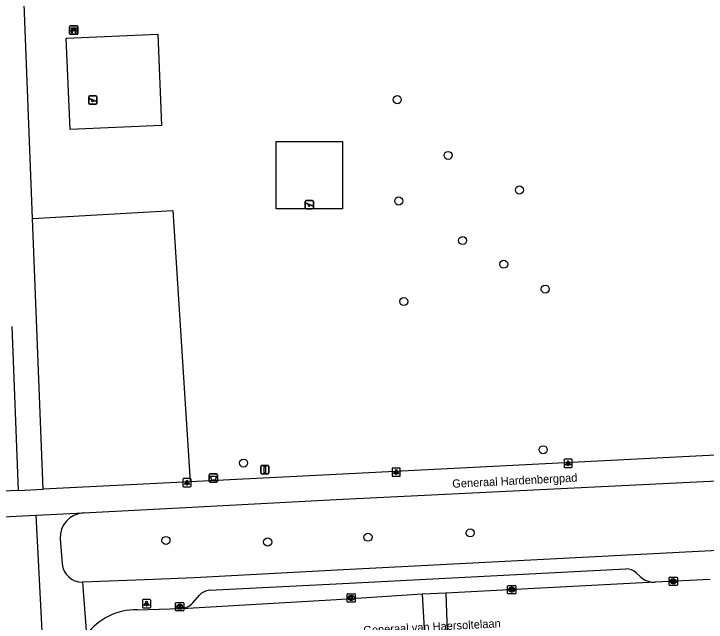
# Model space of a CAD drawing. Extents: x 161084 to 161928, y 385355 to 386522.
# Drawn here: x 161461 to 161544.8, y 386008.9 to 386082.6 of the extents above; entities that cross this region are included whole.
import ezdxf

# ---------------------------------------------------------------- set-up
doc = ezdxf.new("R2010")
doc.units = 0
for name, color, linetype in [('IMGEO_Afvalbak', 7, 'Continuous'), ('IMGEO_Bank', 7, 'Continuous'), ('IMGEO_Boom', 7, 'Continuous'), ('IMGEO_Groenvoorziening', 7, 'Continuous'), ('IMGEO_Kolk', 7, 'Continuous'), ('IMGEO_Lichtpunt', 7, 'Continuous'), ('IMGEO_Openbare_ruimte_label', 7, 'Continuous'), ('IMGEO_Rijbaan_lokaal_open', 7, 'Continuous'), ('IMGEO_Speelvoorziening', 7, 'Continuous'), ('IMGEO_Verkeersbordpaal', 7, 'Continuous'), ('IMGEO_Voetpad_halfverhard', 7, 'Continuous'), ('IMGEO_Voetpad_open', 7, 'Continuous')]:
    doc.layers.add(name, color=color, linetype=linetype)

msp = doc.modelspace()

# ---------------------------------------------------------------- linework, layer by layer
at = {"layer": 'IMGEO_Afvalbak'}
for p, q in [((161484.644, 386025.959), (161484.644, 386026.759)), ((161484.644, 386026.759), (161484.644, 386025.959)), ((161484.744, 386026.859), (161485.534, 386026.859)), ((161485.534, 386026.859), (161484.744, 386026.859)), ((161485.634, 386026.759), (161485.634, 386025.959)), ((161485.634, 386025.959), (161485.634, 386026.759)), ((161485.534, 386025.859), (161484.744, 386025.859)), ((161484.744, 386025.859), (161485.534, 386025.859))]:
    msp.add_line(p, q, dxfattribs=at)
msp.add_lwpolyline([(161484.787, 386026.573), (161485.491, 386026.573), (161485.342, 386026.103), (161484.936, 386026.103), (161484.787, 386026.573)], dxfattribs=at)
for centre, start, end in [((161484.744, 386026.759), 90, 180), ((161484.744, 386026.759), 90, 180), ((161485.534, 386026.759), 0, 90), ((161485.534, 386026.759), 360, 90), ((161484.744, 386025.959), 180, 270), ((161484.744, 386025.959), 180, 270), ((161485.534, 386025.959), 270, 0), ((161485.534, 386025.959), 270, 0)]:
    msp.add_arc(centre, 0.1, start, end, dxfattribs=at)
at = {"layer": 'IMGEO_Bank'}
for p, q in [((161467.729, 386080.215), (161467.729, 386081.056)), ((161467.729, 386081.056), (161467.729, 386080.215)), ((161467.804, 386081.14), (161468.645, 386081.14)), ((161468.645, 386081.14), (161467.804, 386081.14)), ((161468.426, 386080.538), (161468.033, 386080.538)), ((161468.038, 386080.646), (161468.038, 386080.752)), ((161468.082, 386080.752), (161468.082, 386080.646)), ((161468.37, 386080.758), (161468.088, 386080.758)), ((161468.088, 386080.64), (161468.37, 386080.64)), ((161468.376, 386080.646), (161468.376, 386080.752)), ((161468.42, 386080.752), (161468.42, 386080.646)), ((161468.729, 386081.065), (161468.729, 386080.224)), ((161468.729, 386080.224), (161468.729, 386081.065)), ((161468.654, 386080.14), (161467.813, 386080.14)), ((161467.813, 386080.14), (161468.654, 386080.14))]:
    msp.add_line(p, q, dxfattribs=at)
for points in [[(161467.976, 386080.538), (161467.834, 386080.538), (161467.946, 386080.64), (161468.032, 386080.64)], [(161468.032, 386080.758), (161467.946, 386080.758), (161467.946, 386080.919), (161468.509, 386080.919), (161468.509, 386080.758), (161468.426, 386080.758)], [(161468.026, 386080.531), (161468.026, 386080.324), (161467.983, 386080.324), (161467.983, 386080.531)], [(161468.426, 386080.64), (161468.509, 386080.64), (161468.621, 386080.538), (161468.482, 386080.538)], [(161468.476, 386080.531), (161468.476, 386080.324), (161468.432, 386080.324), (161468.432, 386080.531)]]:
    msp.add_lwpolyline(points, dxfattribs=at)
for centre, radius, start, end in [((161467.807, 386081.062), 0.0779, 92.4484, 184.28452), ((161467.807, 386081.062), 0.0779, 92.4484, 184.28452), ((161467.976, 386080.531), 0.00671, 2.89567, 87.10433), ((161468.033, 386080.531), 0.00671, 92.89567, 177.10433), ((161468.031, 386080.751), 0.00671, 2.89567, 87.10433), ((161468.031, 386080.647), 0.00671, 272.89567, 357.10433), ((161468.088, 386080.751), 0.00671, 92.89567, 177.10433), ((161468.088, 386080.647), 0.00671, 182.89567, 267.10433), ((161468.37, 386080.751), 0.00671, 2.89567, 87.10433), ((161468.37, 386080.647), 0.00671, 272.89567, 357.10433), ((161468.427, 386080.751), 0.00671, 92.89567, 177.10433), ((161468.427, 386080.647), 0.00671, 182.89567, 267.10433), ((161468.425, 386080.531), 0.00671, 2.89567, 87.10433), ((161468.482, 386080.531), 0.00671, 92.89567, 177.10433), ((161468.651, 386081.062), 0.0779, 2.4484, 94.28452), ((161468.651, 386081.062), 0.0779, 2.4484, 94.28452), ((161467.807, 386080.218), 0.0779, 182.4484, 274.28452), ((161467.807, 386080.218), 0.0779, 182.4484, 274.28452), ((161468.651, 386080.218), 0.0779, 272.4484, 4.28452), ((161468.651, 386080.218), 0.0779, 272.4484, 4.28452)]:
    msp.add_arc(centre, radius, start, end, dxfattribs=at)
at = {"layer": 'IMGEO_Boom'}
for centre in [(161507.41, 386072.212), (161513.567, 386065.457), (161522.204, 386061.262), (161507.588, 386059.932), (161515.323, 386055.142), (161520.306, 386052.275), (161525.328, 386049.255), (161508.198, 386047.752), (161525.077, 386029.792), (161488.796, 386028.181), (161516.246, 386019.719), (161479.401, 386018.801), (161503.865, 386019.196), (161491.714, 386018.614)]:
    msp.add_circle(centre, 0.489, dxfattribs=at)
at = {"layer": 'IMGEO_Groenvoorziening'}
for points in [[(161478.879, 386069.064), (161467.783, 386068.585), (161467.317, 386079.672), (161478.424, 386080.161), (161478.879, 386069.064)], [(161492.761, 386067.136), (161500.761, 386067.136), (161500.761, 386058.992), (161492.761, 386058.992), (161492.761, 386067.136)], [(161463.243, 386057.808), (161480.224, 386058.791), (161482.316, 386025.914)]]:
    msp.add_lwpolyline(points, dxfattribs=at)
at = {"layer": 'IMGEO_Kolk'}
for p, q in [((161540.329, 386013.423), (161540.329, 386014.275)), ((161540.404, 386014.349), (161541.256, 386014.349)), ((161541.33, 386014.275), (161541.33, 386013.423)), ((161520.848, 386013.344), (161521.7, 386013.344)), ((161541.256, 386013.349), (161540.404, 386013.349)), ((161540.84, 386013.569), (161540.815, 386013.569)), ((161540.817, 386014.129), (161540.842, 386014.129)), ((161520.773, 386012.418), (161520.773, 386013.27)), ((161521.284, 386012.564), (161521.259, 386012.564)), ((161521.261, 386013.124), (161521.286, 386013.124)), ((161521.774, 386013.27), (161521.774, 386012.418)), ((161501.326, 386011.412), (161501.326, 386012.264)), ((161501.401, 386012.338), (161502.253, 386012.338)), ((161501.814, 386012.118), (161501.839, 386012.118)), ((161502.327, 386012.264), (161502.327, 386011.412)), ((161521.7, 386012.344), (161520.848, 386012.344)), ((161480.572, 386010.351), (161480.572, 386011.203)), ((161480.647, 386011.277), (161481.499, 386011.277)), ((161481.06, 386011.057), (161481.085, 386011.057)), ((161481.573, 386011.203), (161481.573, 386010.351)), ((161502.253, 386011.338), (161501.401, 386011.338)), ((161501.837, 386011.558), (161501.812, 386011.558)), ((161481.499, 386010.277), (161480.647, 386010.277)), ((161481.083, 386010.497), (161481.058, 386010.497))]:
    msp.add_line(p, q, dxfattribs=at)
for points in [[(161540.329, 386013.423), (161540.329, 386014.275)], [(161540.404, 386014.349), (161541.256, 386014.349)], [(161541.33, 386014.275), (161541.33, 386013.423)], [(161520.848, 386013.344), (161521.7, 386013.344)], [(161541.256, 386013.349), (161540.404, 386013.349)], [(161540.65, 386014.049), (161540.773, 386014.049), (161540.773, 386013.898), (161540.903, 386014.049), (161541.067, 386014.049), (161540.921, 386013.898), (161541.074, 386013.649), (161540.922, 386013.649), (161540.837, 386013.813), (161540.773, 386013.746), (161540.773, 386013.649), (161540.65, 386013.649), (161540.65, 386014.049)], [(161520.773, 386012.418), (161520.773, 386013.27)], [(161521.094, 386013.044), (161521.217, 386013.044), (161521.217, 386012.893), (161521.347, 386013.044), (161521.511, 386013.044), (161521.365, 386012.893), (161521.518, 386012.644), (161521.366, 386012.644), (161521.281, 386012.808), (161521.217, 386012.741), (161521.217, 386012.644), (161521.094, 386012.644), (161521.094, 386013.044)], [(161521.774, 386013.27), (161521.774, 386012.418)], [(161501.326, 386011.412), (161501.326, 386012.264)], [(161501.401, 386012.338), (161502.253, 386012.338)], [(161501.647, 386012.038), (161501.77, 386012.038), (161501.77, 386011.887), (161501.9, 386012.038), (161502.064, 386012.038), (161501.918, 386011.887), (161502.071, 386011.638), (161501.919, 386011.638), (161501.834, 386011.802), (161501.77, 386011.735), (161501.77, 386011.638), (161501.647, 386011.638), (161501.647, 386012.038)], [(161502.327, 386012.264), (161502.327, 386011.412)], [(161521.7, 386012.344), (161520.848, 386012.344)], [(161480.572, 386010.351), (161480.572, 386011.203)], [(161480.647, 386011.277), (161481.499, 386011.277)], [(161480.893, 386010.977), (161481.016, 386010.977), (161481.016, 386010.826), (161481.146, 386010.977), (161481.31, 386010.977), (161481.164, 386010.826), (161481.317, 386010.577), (161481.165, 386010.577), (161481.08, 386010.741), (161481.016, 386010.674), (161481.016, 386010.577), (161480.893, 386010.577), (161480.893, 386010.977)], [(161481.573, 386011.203), (161481.573, 386010.351)], [(161502.253, 386011.338), (161501.401, 386011.338)], [(161481.499, 386010.277), (161480.647, 386010.277)]]:
    msp.add_lwpolyline(points, dxfattribs=at)
for centre, start, end in [((161540.406, 386014.273), 91.55205, 178.44795), ((161540.406, 386014.273), 91.55205, 178.44795), ((161541.254, 386014.273), 1.55205, 88.44795), ((161541.254, 386014.273), 1.55205, 88.44795), ((161520.85, 386013.268), 91.55205, 178.44795), ((161520.85, 386013.268), 91.55205, 178.44795), ((161521.698, 386013.268), 1.55205, 88.44795), ((161521.698, 386013.268), 1.55205, 88.44795), ((161540.406, 386013.425), 181.55205, 268.44795), ((161540.406, 386013.425), 181.55205, 268.44795), ((161541.254, 386013.425), 271.55205, 358.44795), ((161541.254, 386013.425), 271.55205, 358.44795), ((161501.403, 386012.262), 91.55205, 178.44795), ((161501.403, 386012.262), 91.55205, 178.44795), ((161502.251, 386012.262), 1.55205, 88.44795), ((161502.251, 386012.262), 1.55205, 88.44795), ((161520.85, 386012.42), 181.55205, 268.44795), ((161520.85, 386012.42), 181.55205, 268.44795), ((161521.698, 386012.42), 271.55205, 358.44795), ((161521.698, 386012.42), 271.55205, 358.44795), ((161480.649, 386011.201), 91.55205, 178.44795), ((161480.649, 386011.201), 91.55205, 178.44795), ((161481.497, 386011.201), 1.55205, 88.44795), ((161481.497, 386011.201), 1.55205, 88.44795), ((161501.403, 386011.414), 181.55205, 268.44795), ((161501.403, 386011.414), 181.55205, 268.44795), ((161502.251, 386011.414), 271.55205, 358.44795), ((161502.251, 386011.414), 271.55205, 358.44795), ((161480.649, 386010.353), 181.55205, 268.44795), ((161480.649, 386010.353), 181.55205, 268.44795), ((161481.497, 386010.353), 271.55205, 358.44795), ((161481.497, 386010.353), 271.55205, 358.44795)]:
    msp.add_arc(centre, 0.0765, start, end, dxfattribs=at)
for centre, major_axis, ratio, start_param, end_param in [((161540.816, 386013.849), (-0.387, 0.002), 0.722429, 4.712389, 7.853982), ((161540.841, 386013.849), (-0.39, 0.002), 0.717154, 1.570796, 4.712389), ((161521.26, 386012.844), (-0.387, 0.002), 0.722429, 4.712389, 7.853982), ((161521.285, 386012.844), (-0.39, 0.002), 0.717154, 1.570796, 4.712389), ((161501.813, 386011.838), (-0.387, 0.002), 0.722429, 4.712389, 7.853982), ((161501.838, 386011.838), (-0.39, 0.002), 0.717154, 1.570796, 4.712389), ((161481.059, 386010.777), (-0.387, 0.002), 0.722429, 4.712389, 7.853982), ((161481.084, 386010.777), (-0.39, 0.002), 0.717154, 1.570796, 4.712389)]:
    msp.add_ellipse(centre, major_axis=major_axis, ratio=ratio, start_param=start_param, end_param=end_param, dxfattribs=at)
at = {"layer": 'IMGEO_Lichtpunt'}
for p, q in [((161527.602, 386028.54), (161527.602, 386027.733)), ((161527.602, 386028.54), (161527.602, 386027.733)), ((161528.504, 386028.635), (161527.696, 386028.635)), ((161528.504, 386028.635), (161527.696, 386028.635)), ((161528.598, 386027.733), (161528.598, 386028.54)), ((161528.598, 386027.733), (161528.598, 386028.54)), ((161507.68, 386027.579), (161506.872, 386027.579)), ((161507.68, 386027.579), (161506.872, 386027.579)), ((161527.696, 386027.639), (161528.504, 386027.639)), ((161527.696, 386027.639), (161528.504, 386027.639)), ((161506.778, 386027.484), (161506.778, 386026.677)), ((161506.778, 386027.484), (161506.778, 386026.677)), ((161507.774, 386026.677), (161507.774, 386027.484)), ((161507.774, 386026.677), (161507.774, 386027.484)), ((161481.44, 386026.198), (161481.44, 386025.391)), ((161481.44, 386026.198), (161481.44, 386025.391)), ((161482.342, 386026.293), (161481.534, 386026.293)), ((161482.342, 386026.293), (161481.534, 386026.293)), ((161482.436, 386025.391), (161482.436, 386026.198)), ((161482.436, 386025.391), (161482.436, 386026.198)), ((161506.872, 386026.583), (161507.68, 386026.583)), ((161506.872, 386026.583), (161507.68, 386026.583)), ((161481.534, 386025.297), (161482.342, 386025.297)), ((161481.534, 386025.297), (161482.342, 386025.297)), ((161477.455, 386011.633), (161476.647, 386011.633)), ((161477.455, 386011.633), (161476.647, 386011.633)), ((161476.553, 386011.538), (161476.553, 386010.731)), ((161476.553, 386011.538), (161476.553, 386010.731)), ((161477.549, 386010.731), (161477.549, 386011.538)), ((161477.549, 386010.731), (161477.549, 386011.538)), ((161476.647, 386010.637), (161477.455, 386010.637)), ((161476.647, 386010.637), (161477.455, 386010.637))]:
    msp.add_line(p, q, dxfattribs=at)
for points in [[(161527.976, 386028.204), (161528.015, 386028.176), (161527.827, 386027.914), (161527.789, 386027.941), (161527.976, 386028.204)], [(161528.078, 386028.156), (161528.125, 386028.156), (161528.125, 386027.834), (161528.078, 386027.834), (161528.078, 386028.156)], [(161528.188, 386028.176), (161528.226, 386028.203), (161528.413, 386027.941), (161528.374, 386027.913), (161528.188, 386028.176)], [(161507.152, 386027.148), (161507.191, 386027.12), (161507.003, 386026.858), (161506.965, 386026.885), (161507.152, 386027.148)], [(161507.254, 386027.1), (161507.301, 386027.1), (161507.301, 386026.778), (161507.254, 386026.778), (161507.254, 386027.1)], [(161507.364, 386027.12), (161507.402, 386027.147), (161507.589, 386026.885), (161507.55, 386026.857), (161507.364, 386027.12)], [(161481.814, 386025.862), (161481.853, 386025.834), (161481.665, 386025.572), (161481.627, 386025.599), (161481.814, 386025.862)], [(161481.916, 386025.814), (161481.963, 386025.814), (161481.963, 386025.492), (161481.916, 386025.492), (161481.916, 386025.814)], [(161482.026, 386025.834), (161482.064, 386025.861), (161482.251, 386025.599), (161482.212, 386025.571), (161482.026, 386025.834)], [(161476.927, 386011.202), (161476.966, 386011.174), (161476.778, 386010.912), (161476.74, 386010.939), (161476.927, 386011.202)], [(161477.029, 386011.154), (161477.076, 386011.154), (161477.076, 386010.832), (161477.029, 386010.832), (161477.029, 386011.154)], [(161477.139, 386011.174), (161477.177, 386011.201), (161477.364, 386010.939), (161477.325, 386010.911), (161477.139, 386011.174)]]:
    msp.add_lwpolyline(points, dxfattribs=at)
for centre in [(161528.101, 386028.338), (161507.277, 386027.282), (161481.939, 386025.996), (161477.052, 386011.336)]:
    msp.add_circle(centre, 0.0994, dxfattribs=at)
for centre, start, end in [((161527.696, 386028.54), 90, 180), ((161527.696, 386028.54), 90, 180), ((161528.504, 386028.54), 0, 90), ((161528.504, 386028.54), 0, 90), ((161506.872, 386027.484), 90, 180), ((161506.872, 386027.484), 90, 180), ((161507.68, 386027.484), 0, 90), ((161507.68, 386027.484), 0, 90), ((161527.696, 386027.733), 180, 270), ((161527.696, 386027.733), 180, 270), ((161528.504, 386027.733), 270, 0), ((161528.504, 386027.733), 270, 360), ((161481.534, 386026.198), 90, 180), ((161481.534, 386026.198), 90, 180), ((161482.342, 386026.198), 0, 90), ((161482.342, 386026.198), 0, 90), ((161506.872, 386026.677), 180, 270), ((161506.872, 386026.677), 180, 270), ((161507.68, 386026.677), 270, 0), ((161507.68, 386026.677), 270, 360), ((161481.534, 386025.391), 180, 270), ((161481.534, 386025.391), 180, 270), ((161482.342, 386025.391), 270, 0), ((161482.342, 386025.391), 270, 360), ((161476.647, 386011.538), 90, 180), ((161476.647, 386011.538), 90, 180), ((161477.455, 386011.538), 0, 90), ((161477.455, 386011.538), 0, 90), ((161476.647, 386010.731), 180, 270), ((161476.647, 386010.731), 180, 270), ((161477.455, 386010.731), 270, 0), ((161477.455, 386010.731), 270, 360)]:
    msp.add_arc(centre, 0.0946, start, end, dxfattribs=at)
at = {"layer": 'IMGEO_Rijbaan_lokaal_open'}
for points in [[(161538.652, 386013.734), (161513.282, 386012.427)], [(161545.29, 386014.076), (161538.652, 386013.734)], [(161510.441, 386012.28), (161500.065, 386011.599), (161481.314, 386010.537), (161481.203, 386010.561)], [(161513.282, 386012.427), (161510.441, 386012.28)], [(161510.441, 386012.28), (161510.848, 386005.259)], [(161513.282, 386012.427), (161513.535, 386005.395)], [(161475.938, 386010.38), (161481.203, 386010.561)]]:
    msp.add_lwpolyline(points, dxfattribs=at)
msp.add_arc((161475.713, 386003.075), 7.309, 88.2387, 144.287, dxfattribs=at)
at = {"layer": 'IMGEO_Speelvoorziening'}
for p, q in [((161470.047, 386071.758), (161470.047, 386072.558)), ((161470.047, 386072.558), (161470.047, 386071.758)), ((161470.43, 386072.186), (161470.091, 386072.323)), ((161470.116, 386072.383), (161470.992, 386072.03)), ((161470.147, 386072.658), (161470.937, 386072.658)), ((161470.937, 386072.658), (161470.147, 386072.658)), ((161470.968, 386071.97), (161470.628, 386072.107)), ((161471.037, 386072.558), (161471.037, 386071.758)), ((161471.037, 386071.758), (161471.037, 386072.558)), ((161470.937, 386071.658), (161470.147, 386071.658)), ((161470.147, 386071.658), (161470.937, 386071.658)), ((161496.266, 386059.092), (161496.266, 386059.892)), ((161496.266, 386059.892), (161496.266, 386059.092)), ((161496.649, 386059.52), (161496.31, 386059.657)), ((161496.335, 386059.717), (161497.211, 386059.364)), ((161496.366, 386059.992), (161497.156, 386059.992)), ((161497.156, 386059.992), (161496.366, 386059.992)), ((161497.187, 386059.304), (161496.847, 386059.441)), ((161497.256, 386059.892), (161497.256, 386059.092)), ((161497.256, 386059.092), (161497.256, 386059.892)), ((161497.156, 386058.992), (161496.366, 386058.992)), ((161496.366, 386058.992), (161497.156, 386058.992))]:
    msp.add_line(p, q, dxfattribs=at)
for centre, radius, start, end in [((161470.147, 386072.558), 0.1, 90, 180), ((161470.147, 386072.558), 0.1, 90, 180), ((161470.104, 386072.353), 0.0327, 68.07798, 248.07798), ((161470.509, 386072.096), 0.12, 130.99278, 5.16318), ((161470.937, 386072.558), 0.1, 0, 90), ((161470.937, 386072.558), 0.1, 360, 90), ((161470.98, 386072), 0.0327, 248.07798, 68.07798), ((161470.147, 386071.758), 0.1, 180, 270), ((161470.147, 386071.758), 0.1, 180, 270), ((161470.937, 386071.758), 0.1, 270, 0), ((161470.937, 386071.758), 0.1, 270, 0), ((161496.366, 386059.892), 0.1, 90, 180), ((161496.366, 386059.892), 0.1, 90, 180), ((161496.323, 386059.687), 0.0327, 68.07798, 248.07798), ((161496.728, 386059.43), 0.12, 130.99278, 5.16318), ((161497.156, 386059.892), 0.1, 0, 90), ((161497.156, 386059.892), 0.1, 360, 90), ((161496.366, 386059.092), 0.1, 180, 270), ((161496.366, 386059.092), 0.1, 180, 270), ((161497.156, 386059.092), 0.1, 270, 0), ((161497.156, 386059.092), 0.1, 270, 0), ((161497.199, 386059.334), 0.0327, 248.07798, 68.07798)]:
    msp.add_arc(centre, radius, start, end, dxfattribs=at)
at = {"layer": 'IMGEO_Verkeersbordpaal'}
for p, q in [((161490.872, 386026.982), (161490.872, 386027.782)), ((161490.872, 386027.782), (161490.872, 386026.982)), ((161490.972, 386027.882), (161491.762, 386027.882)), ((161491.762, 386027.882), (161490.972, 386027.882)), ((161491.862, 386027.782), (161491.862, 386026.982)), ((161491.862, 386026.982), (161491.862, 386027.782)), ((161491.762, 386026.882), (161490.972, 386026.882)), ((161490.972, 386026.882), (161491.762, 386026.882))]:
    msp.add_line(p, q, dxfattribs=at)
msp.add_lwpolyline([(161491.292, 386027.757), (161491.442, 386027.757), (161491.442, 386027.007), (161491.292, 386027.007), (161491.292, 386027.757)], dxfattribs=at)
for centre, start, end in [((161490.972, 386027.782), 90, 180), ((161490.972, 386027.782), 90, 180), ((161491.762, 386027.782), 0, 90), ((161491.762, 386027.782), 360, 90), ((161490.972, 386026.982), 180, 270), ((161490.972, 386026.982), 180, 270), ((161491.762, 386026.982), 270, 0), ((161491.762, 386026.982), 270, 0)]:
    msp.add_arc(centre, 0.1, start, end, dxfattribs=at)
at = {"layer": 'IMGEO_Voetpad_halfverhard'}
for points in [[(161463.243, 386057.808), (161461.468, 386103.571)], [(161464.514, 386025.016), (161463.243, 386057.808)], [(161460.731, 386044.726), (161461.522, 386024.865)]]:
    msp.add_lwpolyline(points, dxfattribs=at)
at = {"layer": 'IMGEO_Voetpad_open'}
for points in [[(161548.34, 386029.265), (161500, 386026.811), (161482.316, 386025.914)], [(161482.316, 386025.914), (161464.514, 386025.016)], [(161469.404, 386022.145), (161482.526, 386022.846), (161500, 386023.757), (161551.917, 386026.309)], [(161461.522, 386024.865), (161452.284, 386024.469), (161451.258, 386024.424)], [(161461.522, 386024.865), (161464.514, 386025.016)], [(161414.464, 386019.403), (161463.668, 386021.852)], [(161463.668, 386021.852), (161469.404, 386022.145)], [(161464.853, 385998.993), (161464.802, 386000), (161463.668, 386021.852)], [(161466.584, 386019.001), (161466.824, 386015.968)], [(161552.483, 386017.898), (161500.133, 386015.215), (161482.799, 386014.271), (161477.873, 386014.079), (161469.279, 386013.763)], [(161484.682, 386012.763), (161500, 386013.547), (161535.092, 386015.357)], [(161536.356, 386014.886), (161536.832, 386014.429)], [(161469.279, 386013.763), (161469.779, 386007.341)], [(161482.635, 386011.253), (161483.452, 386012.188)]]:
    msp.add_lwpolyline(points, dxfattribs=at)
for centre, radius, start, end in [((161469.595, 386019.137), 3.014, 93.64009, 182.5791), ((161469.262, 386016.213), 2.45, 185.74419, 270.39754), ((161535.179, 386013.658), 1.701, 46.20832, 92.91822), ((161538.559, 386016.22), 2.488, 226.04981, 272.14966), ((161484.883, 386010.73), 2.043, 95.64304, 134.46723), ((161481.132, 386012.535), 1.976, 272.05488, 319.52853)]:
    msp.add_arc(centre, radius, start, end, dxfattribs=at)

# ---------------------------------------------------------------- texts
at = {"layer": 'IMGEO_Openbare_ruimte_label'}
for s, rotation, p in [('Generaal Hardenbergpad', 2.86527, (161514.096, 386025.176)), ('Generaal van Haersoltelaan', 2.97967, (161503.33, 386007.419))]:
    msp.add_text(s, height=1, rotation=rotation, dxfattribs=at).set_placement(p)

doc.saveas('drawing.dxf')
